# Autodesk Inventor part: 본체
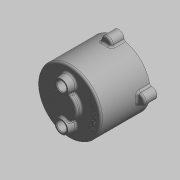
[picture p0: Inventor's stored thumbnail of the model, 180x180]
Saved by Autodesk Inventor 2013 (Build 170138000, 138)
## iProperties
Created: 2015-11
Part Number: 본체
Document SubType Name: 모델링
Designer: mdu
Material: 일반
Density: 1 g/cm^3
변환 표준: STEP AP214IS
파일 이름: C:\Users\SeoGD\Desktop\?쒗뿕\紐몄껜.stp
전처리기: Build: 253, Release: 2010 SP1 - Date: Wed 07/29/2009
전송 단위: 밀리미터
불확실성: 0.01
Author: mdu
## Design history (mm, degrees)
sketch "스케치2"
  geometry: C1 r 50 at (0, 0); 1 further point
  constraints: 1 centre point, 1 coincident
  dimensions: "d9" = 100 diameter of C1
extrude "돌출2" new body sketch "스케치2" distance "d10" = 78.5; taper "d11" = 0 deg
feature "쉘1" dims "d12" = 5
sketch "스케치3" dims "d13" = 55
  geometry: C1 r 7.5 at (0, 27.5); C2 r 12.5 at (0, 27.5); 2 further points
  constraints: 2 centre point, 2 coincident, 2 vertical alignment, 2 other
  dimensions: "d14" = 15 diameter of C1; "d15" = 25 diameter of C2
extrude "돌출3" join sketch "스케치3" distance "d16" = 12; taper "d17" = -10 deg
hole "구멍2" diameter "d20" = 15; stored, may be unused: countersink angle "d24" = 90 deg, drill point angle "d26" = 118 deg; dims "d18" = 10, "d19" = 10, "d21" = 6, "d22" = 4, "d23" = 2, "d25" = 15
chamfer "모따기1" distance "d27" = 1; stored, may be unused: second distance "d28" = 2, angle "d29" = 45 deg
sketch "스케치4"
  geometry: L1 (0, 0)-(0, 86.5); L2 (0, 68.5)-(13.16, 68.5); L3 (-45, 73.5)-(45, 73.5) reference; L4 (-50, 78.5)-(50, 78.5) reference; L5 (13.16, 68.5)-(14.5, 73.5); L6 (20, 78.5)-(20, 86.5); L7 (20, 86.5)-(0, 86.5); L8 (20, 78.5)-(14.5, 73.5)
  constraints: 12 end point, 3 point on line, 2 perpendicular, 1 vertical
  dimensions: "d34" = 40 diameter of L6 L1; "d35" = 105 deg angle of L5 L3; "d36" = 5 distance between parallel lines of L2 L3; "d37" = 8 distance between parallel lines of L7 L4; "d51" = 29 diameter of L5.end L1
revolve "회전1" sketch "스케치4" stored, may be unused: angle "d38" = 90 deg
hole "구멍3" diameter "d41" = 15; stored, may be unused: countersink angle "d45" = 90 deg, drill point angle "d47" = 0 deg; dims "d39" = 10, "d40" = 10, "d42" = 6, "d43" = 22, "d44" = 13, "d46" = 15
chamfer "모따기2" distance "d48" = 1; stored, may be unused: second distance "d49" = 2, angle "d50" = 45 deg
fillet "모깎기1" dims "d52" = 3
fillet "모깎기2" dims "d53" = 3, "d72" = 0.2
sketch "스케치5"
  geometry: A1 r 50 centre (0, 0) between (50, 0) and (-8.074, 49.344) reference; A2 r 8.5 centre (0, 52) between (8.074, 49.344) and (-8.074, 49.344); 1 further point
  constraints: 5 point on circle, 1 centre point, 1 horizontal alignment
  dimensions: "d54" = 90 deg dimension on point (0, 0) A2.centre A1.start; "d55" = 52 distance of A2.centre point (0, 0); "d56" = 17 diameter of A2
extrude "돌출4" join sketch "스케치5" distance "d57" = 20; taper "d58" = 0 deg
fillet "모깎기3" dims "d59" = 3
hole "구멍4" diameter "d62" = 4.134; stored, may be unused: countersink angle "d66" = 90 deg, drill point angle "d68" = 118 deg; dims "d60" = 10, "d61" = 10, "d63" = 12, "d64" = 22, "d65" = 13, "d67" = 15
sketch "스케치6"
  geometry: C1 r 47 at (0, 0) reference; C2 r 42.5 at (0, 0); 1 further point
  constraints: 1 centre point, 1 coincident, 1 other
  dimensions: "d73" = 85 diameter of C2
feature "엠보싱1" sketch "스케치6" dims "d74" = 0.5, "d75" = 0
node "솔리드1"
node "솔리드 본체"
node "곡면 본체"
pattern_circular "원형 패턴1" dims "d31" = 360 deg
pattern_circular "원형 패턴2" dims "d70" = 360 deg
node "솔리드2"
